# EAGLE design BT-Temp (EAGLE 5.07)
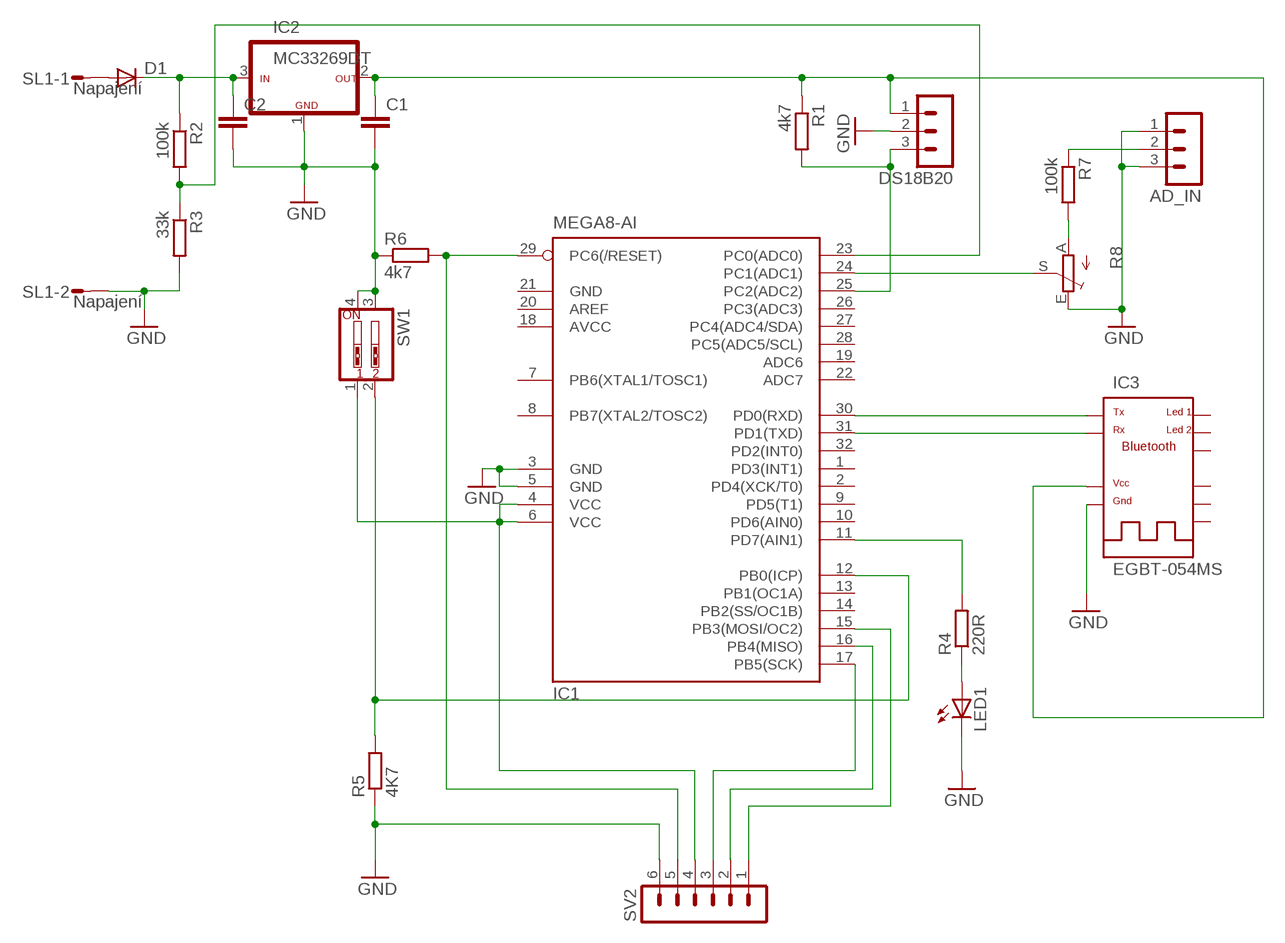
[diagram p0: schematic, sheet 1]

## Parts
AD_IN  MA03-1  [MA03-1]
C1  C-EUC1206  [C1206]
C2  C-EUC1206  [C1206]
D1  DIODE-DO-214AC  [DO-214AC]
DS18B20  MA03-1  [MA03-1]
IC1  MEGA8-AI  [TQFP32-08]
IC2  MC33269DT  [DPACK]
IC3  EGBT-054MS  [EGBT-045MS]
LED1  LED3MM  [LED3MM]
R1  4k7  R-EU_R1206  [R1206]
R2  100k  R-EU_R1206  [R1206]
R3  33k  R-EU_R1206  [R1206]
R4  220R  R-EU_R1206  [R1206]
R5  4K7  R-EU_R1206  [R1206]
R6  4k7  R-EU_R1206  [R1206]
R7  100k  R-EU_R1206  [R1206]
R8  TRIM_EU-CA6V  [CA6V]
SL1  Napajení  M02S  [02P]
SV2  MA06-1  [MA06-1]
SW1  SW_DIP-2  [EDG-02]

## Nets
GND: AD_IN.1 AD_IN.3 C1.2 C2.2 DS18B20.2 IC1.3(GND) IC1.5(GND) IC2.1 IC3.13-GND(GND) LED1.K(C) R3.2 R5.1 R6.1 R8.E SL1.2 SV2.6 SW1.3 SW1.4
N$1: IC1.12(PB0(ICP)) R5.2 SW1.2
N$2: DS18B20.3 IC1.25(PC2(ADC2)) R1.2
N$3: C1.1 DS18B20.1 IC2.2 IC3.12-VCC(VCC) R1.1
N$4: IC1.29(PC6(/RESET)) R6.2 SV2.5
N$5: IC1.4(VCC) IC1.6(VCC) SV2.4 SW1.1
N$6: C2.1 D1.C IC2.3 R2.1
N$7: IC1.23(PC0(ADC0)) R2.2 R3.1
N$8: IC1.17(PB5(SCK)) SV2.3
N$9: IC1.16(PB4(MISO)) SV2.2
N$10: IC1.15(PB3(MOSI/OC2)) SV2.1
N$11: LED1.A R4.1
N$12: AD_IN.2 R7.1
N$13: IC1.30(PD0(RXD)) IC3.1-TX(TX)
N$14: IC1.31(PD1(TXD)) IC3.2-RX(RX)
N$15: R7.2 R8.A
N$16: IC1.11(PD7(AIN1)) R4.2
N$17: D1.A SL1.1
N$19: IC1.24(PC1(ADC1)) R8.S
Unconnected: IC1.1(PD3(INT1)) IC1.2(PD4(XCK/T0)) IC1.7(PB6(XTAL1/TOSC1)) IC1.8(PB7(XTAL2/TOSC2)) IC1.9(PD5(T1)) IC1.10(PD6(AIN0)) IC1.13(PB1(OC1A)) IC1.14(PB2(SS/OC1B)) IC1.19(ADC6) IC1.20(AREF) IC1.22(ADC7) IC1.26(PC3(ADC3)) IC1.27(PC4(ADC4/SDA)) IC1.28(PC5(ADC5/SCL)) IC1.32(PD2(INT0)) IC3.11(LED) IC3.33(LED1) IC3.34(LED2) IC3.P$3(LED3) IC3.P$4(LED4) IC3.P$5(LED5)

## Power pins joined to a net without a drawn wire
AVCC: IC1.18(AVCC)
GND: IC1.21(GND)

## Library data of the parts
AD_IN DS18B20 = con-lstb:MA03-1: PIN HEADER
C1 C2 = rcl:C-EU: CAPACITOR, European symbol
D1 = diode:DIODE-: DIODE
IC1 = atmel:MEGA8: MICROCONTROLLER 8 Kbytes FLASH, 1 kbytes SRAM, 512 bytes EEPROM, USART, 6-channel 10 bit ADC, 2-channel 8 bit ADC Pin compatible with Atmega48, ATMega88, ATMega168 Source: avr.lbr
IC2 = kristel:MC33269DT
IC3 = kristel:EGBT-054MS
LED1 = led:LED: LED
R1-R7 = rcl:R-EU_: RESISTOR, European symbol
R8 = pot:TRIM_EU-: POTENTIOMETER
SL1 = con-amp-quick:M02S: AMP QUICK CONNECTOR
SV2 = con-lstb:MA06-1: PIN HEADER
SW1 = special:SW_DIP-2: DIP SWITCH

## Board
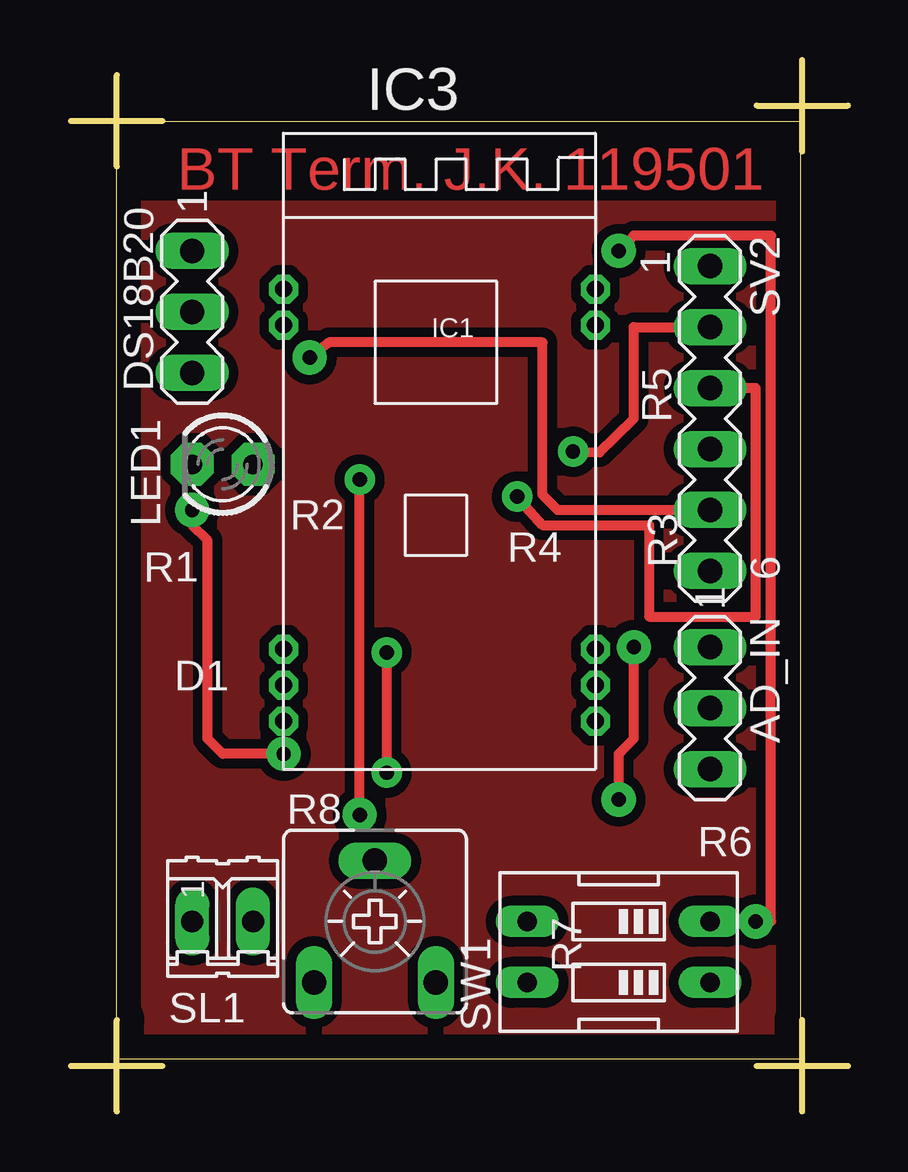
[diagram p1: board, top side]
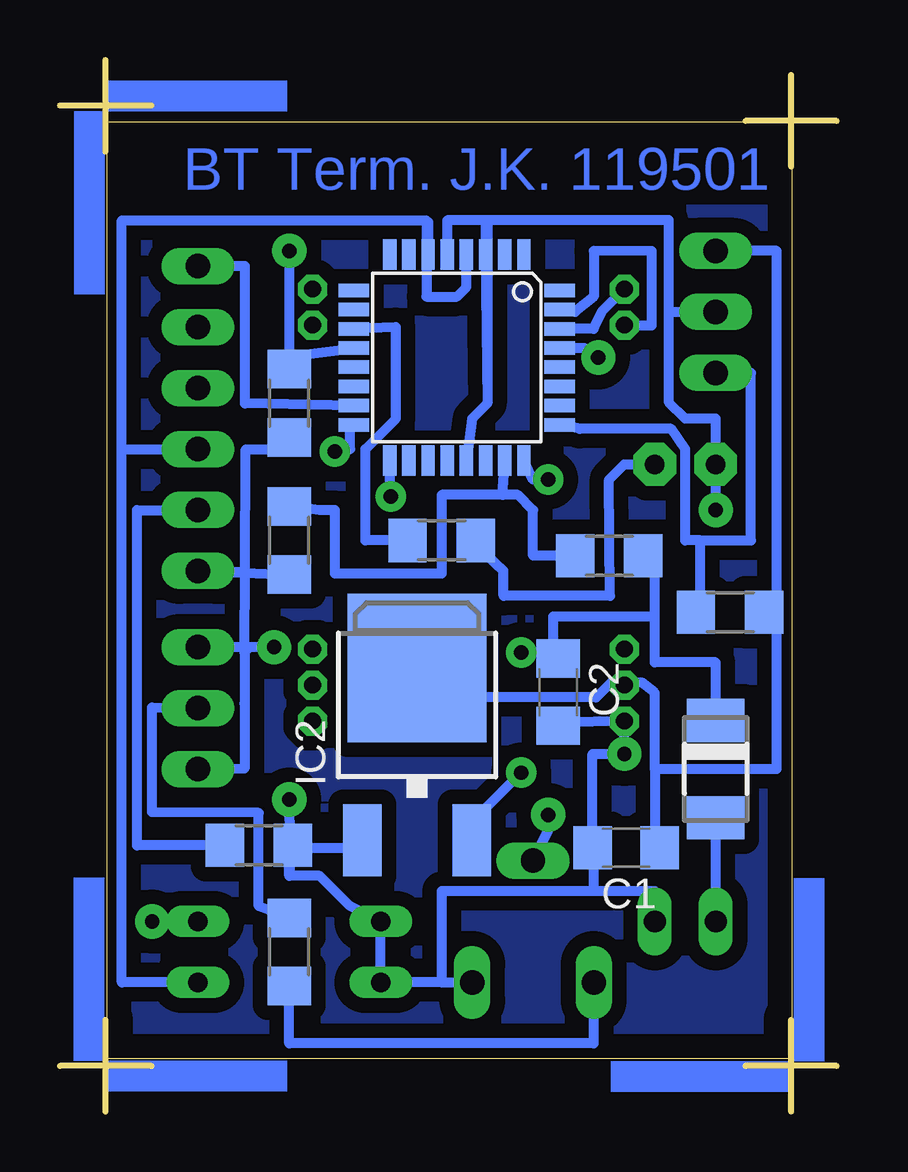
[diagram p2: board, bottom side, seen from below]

Size 32.38 x 43.81 mm. Coordinates in mm from the lower left corner, seen from the top.
Outline: 30.48,40 30.48,43.81
Outline: 28.57,41.91 32.38,41.91
Outline: 30.48,0 30.48,3.81
Outline: 28.57,1.91 32.38,1.91
Outline: 1.91,0 1.91,3.81
Outline: 0,1.91 3.81,1.91
Outline: 1.91,39.37 1.91,43.18
Outline: 0,41.27 3.81,41.27
Outline: 1.87,2.21 30.43,2.21 30.43,41.24 1.87,41.24 1.87,2.21
Copper layers (1*16): Top 0.035mm / dielectric 1.5mm / Bottom 0.035mm
Design rules "default": minimum track width 10mil, minimum drill 24mil, track to track 8mil, track to pad 8mil, pad to pad 8mil, via to via 8mil, smd to smd 8mil, copper to edge 40mil, drill to drill 8mil, minimum pad ring 10mil, minimum via ring 8mil, stop-mask expansion 4mil, vias tented up to drill 0mil, thermal gap 10mil

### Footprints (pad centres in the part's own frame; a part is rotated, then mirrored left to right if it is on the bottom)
MA03-1 = drill 1.016 long: 1 -2.54,0; 2 0,0; 3 2.54,0
C1206 = smd 1.6 x 1.8: 1 -1.4,0; 2 1.4,0
DO-214AC = smd 1.8 x 2.4: A 2.025,0; C -2.025,0
TQFP32-08 = smd 1.27 x 0.559: 1 -4.293,2.8; 2 -4.293,2; 3 -4.293,1.2; 4 -4.293,0.4; 5 -4.293,-0.4; 6 -4.293,-1.2; 7 -4.293,-2; 8 -4.293,-2.8; 17 4.293,-2.8; 18 4.293,-2; 19 4.293,-1.2; 20 4.293,-0.4; 21 4.293,0.4; 22 4.293,1.2; 23 4.293,2; 24 4.293,2.8 | smd 0.559 x 1.27: 9 -2.8,-4.293; 10 -2,-4.293; 11 -1.2,-4.293; 12 -0.4,-4.293; 13 0.4,-4.293; 14 1.2,-4.293; 15 2,-4.293; 16 2.8,-4.293; 25 2.8,4.293; 26 2,4.293; 27 1.2,4.293; 28 0.4,4.293; 29 -0.4,4.293; 30 -1.2,4.293; 31 -2,4.293; 32 -2.8,4.293
DPACK = smd 1.6 x 3: 1 -2.28,-6.07; 3 2.28,-6.07 | smd 5.8 x 6.2: 2 0,1.11
EGBT-045MS = drill 0.7 pad 1.016 octagon: 1-TX 0,20; 2-RX 0,18.5; 11 0,5; 12-VCC 0,3.5; 13-GND 0,2; 33 13,18.5; 34 13,20; P$3 13,5; P$4 13,2; P$5 13,3.5
LED3MM = drill 0.813 pad 1.778 octagon: A -1.27,0; K 1.27,0
R1206 = smd 1.6 x 1.803: 1 -1.422,0; 2 1.422,0
CA6V = drill 1.016 long: A -2.54,-2.54; E 2.54,-2.54; S 0,2.54
02P = drill 0.914 long: 1 -1.27,0; 2 1.27,0
MA06-1 = drill 1.016 long: 1 -6.35,0; 2 -3.81,0; 3 -1.27,0; 4 1.27,0; 5 3.81,0; 6 6.35,0
EDG-02 = drill 0.813 long: 1 -1.27,-3.81; 2 1.27,-3.81; 3 1.27,3.81; 4 -1.27,3.81

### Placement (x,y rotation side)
AD_IN  26.64,16.81 270 top
C1  8.78,10.99 180 bottom
C2  11.61,17.47 270 bottom
D1  5.04,14.27 270 bottom
DS18B20  5.04,33.32 270 top
IC1  15.84,31.41 270 bottom
IC2  17.5,17.37 0 bottom
IC3  8.86,14.27 0 top
LED1  6.32,26.97 180 top
R1  4.45,20.8 180 bottom
R2  9.49,23.16 180 bottom
R3  22.82,23.8 270 bottom
R4  16.48,23.8 180 bottom
R5  22.82,29.51 90 bottom
R6  24.1,11.1 180 bottom
R7  22.82,6.65 270 bottom
R8  12.66,7.92 0 top
SL1  6.32,7.92 0 top
SV2  26.64,28.88 270 top
SW1  22.82,6.65 90 top
U$1  [ANGLE-ARROW-NW1]  30.55,2.12 180 top
U$2  [ANGLE-ARROW-NW1]  30.53,41.67 270 top
U$5  [ANGLE-ARROW-NW1]  1.79,2.1 90 top

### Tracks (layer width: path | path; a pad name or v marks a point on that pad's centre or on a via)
GND  (via drill 0.6 pad 1.42)
  Top 0.406: v5.04,25.06 5.04,24.43 5.68,23.8 5.68,15.54 6.32,14.9 v8.86,14.9 | v22.82,13 22.82,14.9 23.46,15.54 v23.46,19.35
  Bottom 0.406: 7.01,33.32 DS18B20.2 | 7.01,33.32 7.01,37.14 14.57,37.13 | 14.57,37.13 14.64,37.13 | 14.64,37.13 IC1.3 | 14.57,35.71 IC1.3 | 14.57,37.13 14.57,35.71 | 14.64,37.13 16.24,37.13 IC1.5 | 15.44,26.73 IC1.21 15.21,28.88 14.57,29.51 | 16.48,5.38 16.48,9.19 10.12,9.19 | 16.48,5.38 R8.E | SL1.2 7.58,9.19 10.12,9.19 | AD_IN.3 24.69,14.29 24.69,19.13 | 24.69,19.13 24.69,19.34 | 24.69,19.34 AD_IN.1 | 24.69,19.34 24.66,22.48 | 24.66,22.48 SV2.6 R3.2 | R5.1 23.46,27.6 24.64,27.59 24.66,22.48 | IC1.3 14.57,29.51 | 14.57,35.71 14.57,29.51 | 7.01,33.32 6.99,29.54 6.32,28.88 5.04,28.88 LED1.K v5.04,25.06 | 10.12,9.19 10.12,10.36 | 10.12,10.36 10.12,10.99 | R6.1 22.82,10.46 22.82,9.82 | 22.82,9.82 R6.1 | R6.1 22.82,12.37 v22.82,13 | 22.82,9.82 21.55,9.82 20.29,8.55 SW1.3 SW1.4 16.48,5.38 | IC2.1 20.1,10.98 23.19,10.98 23.08,11.1 R6.1 | 10.12,10.36 10.18,10.42 C1.2 10.18,14.9 v8.86,14.9 IC3.13-GND 11.43,16.23 11.43,16.07 C2.2 | 24.69,19.34 24.69,17.01 | v23.46,19.35 24.47,19.35 24.69,19.13
N$1  (via drill 0.6 pad 1.42)
  Top 0.406: v28.54,7.92 29.18,7.92 29.18,36.49 23.46,36.49 v22.82,35.86
  Bottom 0.406: 26,7.92 SW1.2 v28.54,7.92 | IC1.12 22.14,31.55 23.46,31.41 R5.2 v22.82,35.86
N$2
  Bottom 0.406: 5.68,23.8 5.68,20.62 R1.2 | IC1.25 10.71,28.45 6.9,28.45 6.32,27.6 6.32,23.8 5.68,23.8 | 5.68,23.8 3.58,23.8 3.58,30.78 DS18B20.3
N$3
  Bottom 0.406: DS18B20.1 2.5,35.86 2.5,21.26 | 2.5,21.26 3.14,21.41 R1.1 2.5,21.26 | 2.5,21.26 2.5,14.27 7.58,14.27 | 7.38,14.27 7.58,14.32 7.58,14.27 | 7.58,14.27 7.58,11.61 | 7.58,11.61 7.58,10.99 | 7.58,14.27 7.58,17.45 8.14,17.88 IC3.12-VCC 9.39,17.88 10.02,17.25 17.5,17.25 IC2.2 | C1.1 7.38,11.42 7.58,11.61
N$4  (via drill 0.6 pad 1.42)
  Top 0.406: v9.94,31.42 10.76,32.05 19.65,32.05 19.65,25.7 20.29,25.06 SV2.5
  Bottom 0.406: R6.2 29.18,11.1 29.18,25.06 SV2.5 | IC1.29 10.52,31.81 v9.94,31.42
N$5
  Bottom 0.406: IC1.4 15.44,34.35 15.84,33.95 17.11,33.95 17.11,35.78 | 17.11,37.13 17.11,35.78 | 17.11,35.78 IC1.6 17.04,37.06 17.11,37.13 | 17.11,37.13 29.81,37.13 29.81,27.6 | 29.81,27.6 SV2.4 | 29.81,27.6 29.81,5.38 SW1.1
N$6  (via drill 0.6 pad 1.27)
  Top 0.406: v13.16,19.13 v13.16,14.12
  Bottom 0.406: 7.58,20.62 7.58,18.72 5.04,18.72 D1.C | 7.58,20.62 7.58,22.52 R2.1 | 7.58,20.62 11.83,20.62 11.83,18.87 C2.1 11.64,18.87 11.9,19.13 v13.16,19.13 | 15.04,11.61 15.22,11.43 IC2.3 15.04,11.49 15.04,12.24 v13.16,14.12
N$7
  Bottom 0.406: 13.93,25.7 IC1.23 | 13.93,25.7 13.3,25.7 12.66,25.06 12.66,23.16 10.76,23.16 10.76,22.52 11.39,22.52 R2.2 | 13.93,25.7 16.48,25.7 16.48,22.41 20.92,22.41 20.92,25.06 21.55,25.06 R3.1
N$8  (via drill 0.6 pad 1.27)
  Top 0.406: v18.59,25.62 19.65,24.43 24.1,24.43 24.1,20.62 28.54,20.62 28.54,30.15 SV2.3
  Bottom 0.406: IC1.17 18.64,25.96 v18.59,25.62
N$9  (via drill 0.6 pad 1.27)
  Top 0.406: SV2.2 23.46,32.69 23.46,28.88 22.03,27.47 v20.92,27.5
  Bottom 0.406: v20.92,27.5 20.29,27.6 20.29,28.46 IC1.16
N$10
  Bottom 0.406: SV2.1 24.67,35.23 24.67,29.51 IC1.15
N$11
  Bottom 0.406: LED1.A 8.86,26.97 9.49,26.34 9.45,21.49 13.89,21.49 13.9,22.54 14.57,23.16 R4.1
N$12
  Bottom 0.406: AD_IN.2 28.55,16.84 28.55,12.47 24.1,12.45 24.1,8.55 R7.1
N$13
  Bottom 0.406: IC1.30 10.12,32.62 10.12,32.69 9.8,33.32 IC3.1-TX
N$14
  Bottom 0.406: IC3.2-RX 7.71,32.76 7.71,35.85 10.12,35.86 10.12,33.95 10.91,33.32 IC1.31
N$15
  Bottom 0.406: R7.2 22.82,2.84 10.12,2.84 R8.A
N$16
  Bottom 0.406: R4.2 19.65,23.8 19.65,27.6 18.38,28.88 18.38,32.69 IC1.11
N$17
  Bottom 0.406: SL1.1 D1.A
N$18
  pour Top (isolate 0.406): 2.5,37.77 29.81,37.77 29.81,33.95 29.81,2.84 2.5,2.84 2.5,7.29
N$19  (via drill 0.6 pad 1.27, 0.6 pad 1.42)
  Top 0.406: v12.03,12.37 v12.03,26.34
  Bottom 0.406: IC1.24 12.66,26.34 v12.03,26.34 | v12.03,12.37 12.03,11.73 R8.S
N$20
  pour Bottom (isolate 0.61): 2.5,37.77 29.81,37.77 29.81,2.84 2.5,2.84

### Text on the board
Top: BT Term. J.K. 119501
Bottom: BT Term. J.K. 119501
